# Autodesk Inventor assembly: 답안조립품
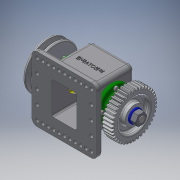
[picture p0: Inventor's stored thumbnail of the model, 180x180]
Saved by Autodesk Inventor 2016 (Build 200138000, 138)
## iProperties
Created: 2018-11
Part Number: 답안조립품
Document SubType Name: Assembly
Designer: Administrator
Author: Administrator
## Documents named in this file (13)
- C:\Users\Administrator\Desktop\481108V1019\답안조립품.iam
- C:\Users\Administrator\Desktop\481108V1019\부품1.ipt
- C:\Users\Administrator\Desktop\481108V1019\이종현\축.ipt
- C:\Users\Administrator\Desktop\481108V1019\이종현\키 5x5x12.ipt
- C:\Users\Administrator\Desktop\481108V1019\이종현\베어링 6203.ipt
- C:\Users\Administrator\Desktop\481108V1019\이종현\오일 실 26 38 8.ipt
- C:\Users\Administrator\Desktop\481108V1019\이종현\커버.ipt
- C:\Users\Administrator\Desktop\481108V1019\이종현\부시.ipt
- C:\Users\Administrator\Desktop\481108V1019\이종현\볼트 M4.ipt
- C:\Users\Administrator\Desktop\481108V1019\이종현\V벨트풀리.ipt
- C:\Users\Administrator\Desktop\481108V1019\이종현\너트 M12x1.25.ipt
- C:\Users\Administrator\Desktop\481108V1019\이종현\와셔 12x24.ipt
- C:\Users\Administrator\Desktop\481108V1019\이종현\스퍼기어.ipt
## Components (1 placed, 1 different names)
1. V벨트풀리:1 — 각도:3
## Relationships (1: Angle 1)
- 각도:3 [Angle]: V벨트풀리:1
